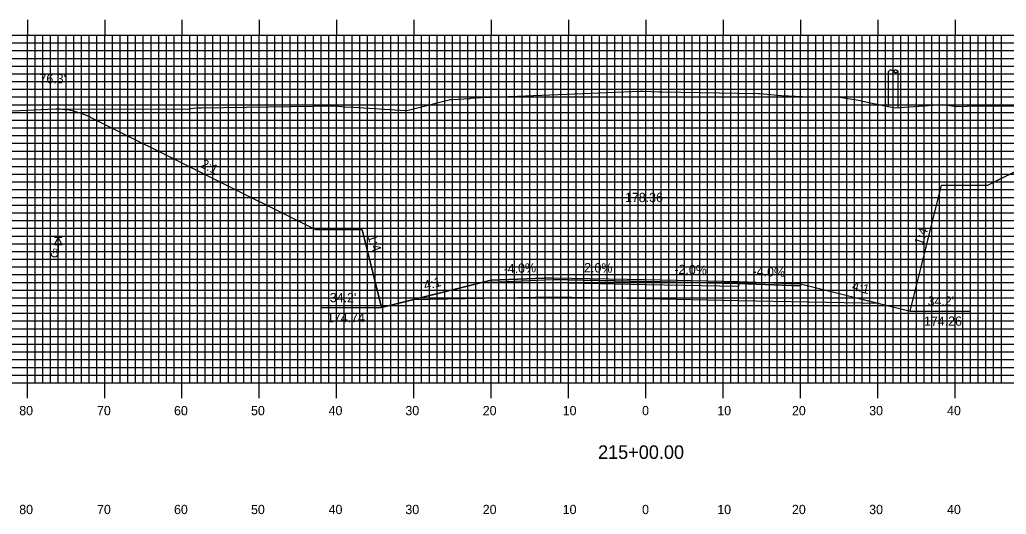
# Model space of a CAD drawing. Extents: x 1796027 to 1796370, y 442591 to 442811.
# Drawn here: x 1796111.4 to 1796239, y 442656.6 to 442720.7 of the extents above; entities that cross this region are included whole.
import ezdxf

# ---------------------------------------------------------------- set-up
doc = ezdxf.new("R2010")
doc.units = 0
for name, color, linetype in [('ANNOTATION', 7, 'Continuous'), ('BORING - REFUSAL', 7, 'Continuous'), ('D_Roadway_Centerline', 7, 'Continuous'), ('D_Roadway_Centerline_Text', 7, 'Continuous'), ('D_Roadway_Edge_Shoulder', 7, 'Continuous'), ('D_Roadway_Edge_TW', 7, 'Continuous'), ('D_Roadway_Pavement', 7, 'Continuous'), ('D_Roadway_SlopeLines', 7, 'Continuous'), ('D_Roadway_SubGrade', 7, 'Continuous'), ('D_Text_Standard', 7, 'Continuous'), ('H_V ANNOTATION', 7, 'Continuous'), ('MAJOR', 7, 'Continuous'), ('MINOR', 7, 'Continuous'), ('PDRAIN', 7, 'Continuous'), ('S_Roadway_Centerline', 7, 'Continuous'), ('S_Utilities_Pole_Power', 7, 'Continuous')]:
    doc.layers.add(name, color=color, linetype=linetype)

msp = doc.modelspace()

# ---------------------------------------------------------------- linework, layer by layer
at = {"layer": 'ANNOTATION'}
for p, q in [((1796236.65, 442699.27), (1796255.09, 442708.49)), ((1796236.65, 442699.27), (1796238.65, 442700.27)), ((1796227.57, 442686.93), (1796230.65, 442699.27)), ((1796230.65, 442699.27), (1796236.65, 442699.27)), ((1796157.22, 442687.41), (1796155.7, 442693.47)), ((1796158.22, 442683.41), (1796157.22, 442687.41)), ((1796226.57, 442682.93), (1796227.57, 442686.93))]:
    msp.add_line(p, q, dxfattribs=at)
msp.add_arc((1796116.09, 442699.09), 10, 63.4349, 90.1255, dxfattribs=at)
msp.add_arc((1796116.09, 442699.09), 10, 63.4349, 90.1255, dxfattribs=at)
at = {"layer": 'BORING - REFUSAL'}
for p, q in [((1796116.87, 442692.47), (1796115.91, 442692.47)), ((1796116.39, 442691.51), (1796116.39, 442690.45))]:
    msp.add_line(p, q, dxfattribs=at)
msp.add_lwpolyline([(1796116.39, 442692.47), (1796116.87, 442691.51), (1796115.91, 442691.51)], close=True, dxfattribs=at)
msp.add_arc((1796115.91, 442690.45), 0.485, 180, 0, dxfattribs=at)
at = {"layer": 'D_Roadway_Centerline'}
msp.add_lwpolyline([(1796155.7, 442693.47), (1796158.22, 442683.41), (1796162.22, 442684.41), (1796172.39, 442686.95), (1796180.39, 442687.27), (1796192.39, 442687.03), (1796204.39, 442686.79), (1796212.39, 442686.47), (1796222.57, 442683.93), (1796226.57, 442682.93), (1796230.65, 442699.27), (1796236.65, 442699.27), (1796255.09, 442708.49)], dxfattribs=at)
at = {"layer": 'D_Roadway_Edge_Shoulder'}
for points in [[(1796180.39, 442687.27), (1796172.39, 442686.95), (1796172.39, 442686.7), (1796180.39, 442687.02)], [(1796204.39, 442686.79), (1796212.39, 442686.47), (1796212.39, 442686.22), (1796204.39, 442686.54)]]:
    msp.add_lwpolyline(points, close=True, dxfattribs=at)
at = {"layer": 'D_Roadway_Edge_TW'}
msp.add_lwpolyline([(1796180.39, 442687.02), (1796180.39, 442687.27), (1796192.39, 442687.03), (1796204.39, 442686.79), (1796204.39, 442686.54), (1796192.39, 442686.78)], close=True, dxfattribs=at)
at = {"layer": 'D_Roadway_Pavement'}
msp.add_lwpolyline([(1796180.39, 442686.6), (1796180.39, 442687.02), (1796192.39, 442686.78), (1796204.39, 442686.54), (1796204.39, 442686.12), (1796192.39, 442686.36)], close=True, dxfattribs=at)
at = {"layer": 'D_Roadway_SlopeLines'}
for points in [[(1796155.7, 442693.47), (1796149.7, 442693.47), (1796120.56, 442708.03)], [(1796172.39, 442686.95), (1796158.22, 442683.41)], [(1796212.39, 442686.47), (1796226.57, 442682.93)]]:
    msp.add_lwpolyline(points, dxfattribs=at)
at = {"layer": 'D_Roadway_SubGrade'}
msp.add_lwpolyline([(1796180.39, 442684.77), (1796162.22, 442684.41), (1796172.39, 442686.95), (1796172.39, 442686.7), (1796180.39, 442687.02), (1796192.39, 442686.78), (1796204.39, 442686.54), (1796212.39, 442686.22), (1796212.39, 442686.47), (1796222.57, 442683.93), (1796204.39, 442684.29), (1796192.39, 442684.53)], close=True, dxfattribs=at)
at = {"layer": 'MAJOR'}
for p, q in [((1796112.39, 442720.67), (1796112.39, 442718.67)), ((1796122.39, 442720.67), (1796122.39, 442718.67)), ((1796132.39, 442720.67), (1796132.39, 442718.67)), ((1796142.39, 442720.67), (1796142.39, 442718.67)), ((1796152.39, 442720.67), (1796152.39, 442718.67)), ((1796162.39, 442720.67), (1796162.39, 442718.67)), ((1796172.39, 442720.67), (1796172.39, 442718.67)), ((1796182.39, 442720.67), (1796182.39, 442718.67)), ((1796192.39, 442720.67), (1796192.39, 442718.67)), ((1796202.39, 442720.67), (1796202.39, 442718.67)), ((1796212.39, 442720.67), (1796212.39, 442718.67)), ((1796222.39, 442720.67), (1796222.39, 442718.67)), ((1796232.39, 442720.67), (1796232.39, 442718.67)), ((1796052.39, 442718.67), (1796332.39, 442718.67)), ((1796052.39, 442718.67), (1796332.39, 442718.67)), ((1796112.39, 442673.67), (1796112.39, 442718.67)), ((1796122.39, 442673.67), (1796122.39, 442718.67)), ((1796132.39, 442673.67), (1796132.39, 442718.67)), ((1796142.39, 442673.67), (1796142.39, 442718.67)), ((1796152.39, 442673.67), (1796152.39, 442718.67)), ((1796162.39, 442673.67), (1796162.39, 442718.67)), ((1796172.39, 442673.67), (1796172.39, 442718.67)), ((1796182.39, 442673.67), (1796182.39, 442718.67)), ((1796192.39, 442673.67), (1796192.39, 442718.67)), ((1796202.39, 442673.67), (1796202.39, 442718.67)), ((1796212.39, 442673.67), (1796212.39, 442718.67)), ((1796222.39, 442673.67), (1796222.39, 442718.67)), ((1796232.39, 442673.67), (1796232.39, 442718.67)), ((1796052.39, 442713.67), (1796332.39, 442713.67)), ((1796052.39, 442708.67), (1796332.39, 442708.67)), ((1796052.39, 442703.67), (1796332.39, 442703.67)), ((1796052.39, 442698.67), (1796332.39, 442698.67)), ((1796052.39, 442693.67), (1796332.39, 442693.67)), ((1796052.39, 442688.67), (1796332.39, 442688.67)), ((1796052.39, 442683.67), (1796332.39, 442683.67)), ((1796052.39, 442678.67), (1796332.39, 442678.67)), ((1796052.39, 442673.67), (1796332.39, 442673.67)), ((1796052.39, 442673.67), (1796332.39, 442673.67)), ((1796112.39, 442671.66), (1796112.39, 442673.67)), ((1796122.39, 442671.66), (1796122.39, 442673.67)), ((1796132.39, 442671.66), (1796132.39, 442673.67)), ((1796142.39, 442671.66), (1796142.39, 442673.67)), ((1796152.39, 442671.66), (1796152.39, 442673.67)), ((1796162.39, 442671.66), (1796162.39, 442673.67)), ((1796172.39, 442671.66), (1796172.39, 442673.67)), ((1796182.39, 442671.66), (1796182.39, 442673.67)), ((1796192.39, 442671.66), (1796192.39, 442673.67)), ((1796202.39, 442671.66), (1796202.39, 442673.67)), ((1796212.39, 442671.66), (1796212.39, 442673.67)), ((1796222.39, 442671.66), (1796222.39, 442673.67)), ((1796232.39, 442671.66), (1796232.39, 442673.67))]:
    msp.add_line(p, q, dxfattribs=at)
at = {"layer": 'MINOR'}
for p, q in [((1796113.39, 442673.67), (1796113.39, 442718.67)), ((1796114.39, 442673.67), (1796114.39, 442718.67)), ((1796115.39, 442673.67), (1796115.39, 442718.67)), ((1796116.39, 442673.67), (1796116.39, 442718.67)), ((1796117.39, 442673.67), (1796117.39, 442718.67)), ((1796118.39, 442673.67), (1796118.39, 442718.67)), ((1796119.39, 442673.67), (1796119.39, 442718.67)), ((1796120.39, 442673.67), (1796120.39, 442718.67)), ((1796121.39, 442673.67), (1796121.39, 442718.67)), ((1796123.39, 442673.67), (1796123.39, 442718.67)), ((1796124.39, 442673.67), (1796124.39, 442718.67)), ((1796125.39, 442673.67), (1796125.39, 442718.67)), ((1796126.39, 442673.67), (1796126.39, 442718.67)), ((1796127.39, 442673.67), (1796127.39, 442718.67)), ((1796128.39, 442673.67), (1796128.39, 442718.67)), ((1796129.39, 442673.67), (1796129.39, 442718.67)), ((1796130.39, 442673.67), (1796130.39, 442718.67)), ((1796131.39, 442673.67), (1796131.39, 442718.67)), ((1796133.39, 442673.67), (1796133.39, 442718.67)), ((1796134.39, 442673.67), (1796134.39, 442718.67)), ((1796135.39, 442673.67), (1796135.39, 442718.67)), ((1796136.39, 442673.67), (1796136.39, 442718.67)), ((1796137.39, 442673.67), (1796137.39, 442718.67)), ((1796138.39, 442673.67), (1796138.39, 442718.67)), ((1796139.39, 442673.67), (1796139.39, 442718.67)), ((1796140.39, 442673.67), (1796140.39, 442718.67)), ((1796141.39, 442673.67), (1796141.39, 442718.67)), ((1796143.39, 442673.67), (1796143.39, 442718.67)), ((1796144.39, 442673.67), (1796144.39, 442718.67)), ((1796145.39, 442673.67), (1796145.39, 442718.67)), ((1796146.39, 442673.67), (1796146.39, 442718.67)), ((1796147.39, 442673.67), (1796147.39, 442718.67)), ((1796148.39, 442673.67), (1796148.39, 442718.67)), ((1796149.39, 442673.67), (1796149.39, 442718.67)), ((1796150.39, 442673.67), (1796150.39, 442718.67)), ((1796151.39, 442673.67), (1796151.39, 442718.67)), ((1796153.39, 442673.67), (1796153.39, 442718.67)), ((1796154.39, 442673.67), (1796154.39, 442718.67)), ((1796155.39, 442673.67), (1796155.39, 442718.67)), ((1796156.39, 442673.67), (1796156.39, 442718.67)), ((1796157.39, 442673.67), (1796157.39, 442718.67)), ((1796158.39, 442673.67), (1796158.39, 442718.67)), ((1796159.39, 442673.67), (1796159.39, 442718.67)), ((1796160.39, 442673.67), (1796160.39, 442718.67)), ((1796161.39, 442673.67), (1796161.39, 442718.67)), ((1796163.39, 442673.67), (1796163.39, 442718.67)), ((1796164.39, 442673.67), (1796164.39, 442718.67)), ((1796165.39, 442673.67), (1796165.39, 442718.67)), ((1796166.39, 442673.67), (1796166.39, 442718.67)), ((1796167.39, 442673.67), (1796167.39, 442718.67)), ((1796168.39, 442673.67), (1796168.39, 442718.67)), ((1796169.39, 442673.67), (1796169.39, 442718.67)), ((1796170.39, 442673.67), (1796170.39, 442718.67)), ((1796171.39, 442673.67), (1796171.39, 442718.67)), ((1796173.39, 442673.67), (1796173.39, 442718.67)), ((1796174.39, 442673.67), (1796174.39, 442718.67)), ((1796175.39, 442673.67), (1796175.39, 442718.67)), ((1796176.39, 442673.67), (1796176.39, 442718.67)), ((1796177.39, 442673.67), (1796177.39, 442718.67)), ((1796178.39, 442673.67), (1796178.39, 442718.67)), ((1796179.39, 442673.67), (1796179.39, 442718.67)), ((1796180.39, 442673.67), (1796180.39, 442718.67)), ((1796181.39, 442673.67), (1796181.39, 442718.67)), ((1796183.39, 442673.67), (1796183.39, 442718.67)), ((1796184.39, 442673.67), (1796184.39, 442718.67)), ((1796185.39, 442673.67), (1796185.39, 442718.67)), ((1796186.39, 442673.67), (1796186.39, 442718.67)), ((1796187.39, 442673.67), (1796187.39, 442718.67)), ((1796188.39, 442673.67), (1796188.39, 442718.67)), ((1796189.39, 442673.67), (1796189.39, 442718.67)), ((1796190.39, 442673.67), (1796190.39, 442718.67)), ((1796191.39, 442673.67), (1796191.39, 442718.67)), ((1796193.39, 442673.67), (1796193.39, 442718.67)), ((1796194.39, 442673.67), (1796194.39, 442718.67)), ((1796195.39, 442673.67), (1796195.39, 442718.67)), ((1796196.39, 442673.67), (1796196.39, 442718.67)), ((1796197.39, 442673.67), (1796197.39, 442718.67)), ((1796198.39, 442673.67), (1796198.39, 442718.67)), ((1796199.39, 442673.67), (1796199.39, 442718.67)), ((1796200.39, 442673.67), (1796200.39, 442718.67)), ((1796201.39, 442673.67), (1796201.39, 442718.67)), ((1796203.39, 442673.67), (1796203.39, 442718.67)), ((1796204.39, 442673.67), (1796204.39, 442718.67)), ((1796205.39, 442673.67), (1796205.39, 442718.67)), ((1796206.39, 442673.67), (1796206.39, 442718.67)), ((1796207.39, 442673.67), (1796207.39, 442718.67)), ((1796208.39, 442673.67), (1796208.39, 442718.67)), ((1796209.39, 442673.67), (1796209.39, 442718.67)), ((1796210.39, 442673.67), (1796210.39, 442718.67)), ((1796211.39, 442673.67), (1796211.39, 442718.67)), ((1796213.39, 442673.67), (1796213.39, 442718.67)), ((1796214.39, 442673.67), (1796214.39, 442718.67)), ((1796215.39, 442673.67), (1796215.39, 442718.67)), ((1796216.39, 442673.67), (1796216.39, 442718.67)), ((1796217.39, 442673.67), (1796217.39, 442718.67)), ((1796218.39, 442673.67), (1796218.39, 442718.67)), ((1796219.39, 442673.67), (1796219.39, 442718.67)), ((1796220.39, 442673.67), (1796220.39, 442718.67)), ((1796221.39, 442673.67), (1796221.39, 442718.67)), ((1796223.39, 442673.67), (1796223.39, 442718.67)), ((1796224.39, 442673.67), (1796224.39, 442718.67)), ((1796225.39, 442673.67), (1796225.39, 442718.67)), ((1796226.39, 442673.67), (1796226.39, 442718.67)), ((1796227.39, 442673.67), (1796227.39, 442718.67)), ((1796228.39, 442673.67), (1796228.39, 442718.67)), ((1796229.39, 442673.67), (1796229.39, 442718.67)), ((1796230.39, 442673.67), (1796230.39, 442718.67)), ((1796231.39, 442673.67), (1796231.39, 442718.67)), ((1796233.39, 442673.67), (1796233.39, 442718.67)), ((1796234.39, 442673.67), (1796234.39, 442718.67)), ((1796235.39, 442673.67), (1796235.39, 442718.67)), ((1796236.39, 442673.67), (1796236.39, 442718.67)), ((1796237.39, 442673.67), (1796237.39, 442718.67)), ((1796238.39, 442673.67), (1796238.39, 442718.67)), ((1796052.39, 442717.67), (1796332.39, 442717.67)), ((1796052.39, 442716.67), (1796332.39, 442716.67)), ((1796052.39, 442715.67), (1796332.39, 442715.67)), ((1796052.39, 442714.67), (1796332.39, 442714.67)), ((1796052.39, 442712.67), (1796332.39, 442712.67)), ((1796052.39, 442711.67), (1796332.39, 442711.67)), ((1796052.39, 442710.67), (1796332.39, 442710.67)), ((1796052.39, 442709.67), (1796332.39, 442709.67)), ((1796052.39, 442707.67), (1796332.39, 442707.67)), ((1796052.39, 442706.67), (1796332.39, 442706.67)), ((1796052.39, 442705.67), (1796332.39, 442705.67)), ((1796052.39, 442704.67), (1796332.39, 442704.67)), ((1796052.39, 442702.67), (1796332.39, 442702.67)), ((1796052.39, 442701.67), (1796332.39, 442701.67)), ((1796052.39, 442700.67), (1796332.39, 442700.67)), ((1796052.39, 442699.67), (1796332.39, 442699.67)), ((1796052.39, 442697.67), (1796332.39, 442697.67)), ((1796052.39, 442696.67), (1796332.39, 442696.67)), ((1796052.39, 442695.67), (1796332.39, 442695.67)), ((1796052.39, 442694.67), (1796332.39, 442694.67)), ((1796052.39, 442692.67), (1796332.39, 442692.67)), ((1796052.39, 442691.67), (1796332.39, 442691.67)), ((1796052.39, 442690.67), (1796332.39, 442690.67)), ((1796052.39, 442689.67), (1796332.39, 442689.67)), ((1796052.39, 442687.67), (1796332.39, 442687.67)), ((1796052.39, 442686.67), (1796332.39, 442686.67)), ((1796052.39, 442685.67), (1796332.39, 442685.67)), ((1796052.39, 442684.67), (1796332.39, 442684.67)), ((1796052.39, 442682.67), (1796332.39, 442682.67)), ((1796052.39, 442681.67), (1796332.39, 442681.67)), ((1796052.39, 442680.67), (1796332.39, 442680.67)), ((1796052.39, 442679.67), (1796332.39, 442679.67)), ((1796052.39, 442677.67), (1796332.39, 442677.67)), ((1796052.39, 442676.67), (1796332.39, 442676.67)), ((1796052.39, 442675.67), (1796332.39, 442675.67)), ((1796052.39, 442674.67), (1796332.39, 442674.67))]:
    msp.add_line(p, q, dxfattribs=at)
at = {"layer": 'PDRAIN'}
for p, q in [((1796150.35, 442683.41), (1796158.22, 442683.41)), ((1796226.57, 442682.93), (1796234.3, 442682.93))]:
    msp.add_line(p, q, dxfattribs=at)
at = {"layer": 'S_Roadway_Centerline'}
msp.add_lwpolyline([(1796110.44, 442708.89), (1796115.06, 442709.09), (1796130.05, 442709.12), (1796132.48, 442709.11), (1796133.28, 442709.13), (1796133.84, 442709.21), (1796134.33, 442709.28), (1796134.89, 442709.27), (1796152.32, 442709.52), (1796153.42, 442709.39), (1796154.62, 442709.37), (1796161.28, 442708.93), (1796161.47, 442708.91), (1796162.69, 442709.21), (1796166.97, 442710.3), (1796167.08, 442710.34), (1796167.43, 442710.35), (1796169.53, 442710.48), (1796169.61, 442710.48), (1796169.77, 442710.52), (1796171.09, 442710.58), (1796174.57, 442710.75), (1796175.73, 442710.79), (1796191.67, 442711.41), (1796191.7, 442711.42), (1796192.04, 442711.41), (1796194.12, 442711.35), (1796194.45, 442711.34), (1796206.92, 442711.1), (1796207.16, 442711.13), (1796209.93, 442710.88), (1796212.65, 442710.71), (1796216.85, 442710.65), (1796217.25, 442710.68), (1796220.13, 442710.22), (1796220.47, 442710.12), (1796221.46, 442709.93), (1796224.63, 442709.28), (1796230.78, 442709.68), (1796232.58, 442709.45), (1796233.96, 442709.48), (1796235.93, 442709.5), (1796236.16, 442709.54), (1796237.54, 442709.5), (1796252.29, 442709.44)], dxfattribs=at)
at = {"layer": 'S_Utilities_Pole_Power'}
for p, q in [((1796223.77, 442713.98), (1796223.93, 442714.09)), ((1796223.77, 442709.36), (1796223.77, 442713.98)), ((1796224.24, 442714.09), (1796224.4, 442713.98)), ((1796224.56, 442714.09), (1796224.4, 442713.98)), ((1796224.4, 442713.98), (1796224.56, 442713.87)), ((1796225.02, 442713.98), (1796224.87, 442714.09)), ((1796224.87, 442713.87), (1796225.02, 442713.98)), ((1796225.02, 442709.36), (1796225.02, 442713.98))]:
    msp.add_line(p, q, dxfattribs=at)
for centre, start, end in [((1796224.09, 442713.87), 90, 125.2644), ((1796224.09, 442713.87), 54.7356, 90), ((1796224.71, 442713.87), 90, 125.2644), ((1796224.71, 442714.09), 234.7356, 270), ((1796224.71, 442713.87), 54.7356, 90), ((1796224.71, 442714.09), 270, 305.2644)]:
    msp.add_arc(centre, 0.271, start, end, dxfattribs=at)

# ---------------------------------------------------------------- texts
at = {"layer": 'ANNOTATION'}
for s, rotation, p in [('2:1', 333.4349, (1796134.7, 442701.62)), ('2:1', 333.4349, (1796134.7, 442701.62)), ('1:4', 70.516, (1796228.2, 442691.38)), ('1:4', 289.484, (1796156.36, 442692.61)), ('-4.0%', 2.2906, (1796174.02, 442687.82)), ('2.0%', 358.8542, (1796184.4, 442687.99)), ('-2.0%', 358.8542, (1796196.08, 442687.76)), ('-4.0%', 357.7094, (1796206.18, 442687.52)), ('4:1', 14.0362, (1796163.84, 442685.67)), ('4:1', 345.9638, (1796218.98, 442685.68))]:
    msp.add_text(s, height=1.2, rotation=rotation, dxfattribs=at).set_placement(p)
for s, p in [("34.2'", (1796151.51, 442684.1)), ("34.2'", (1796228.84, 442683.65)), ('174.74', (1796151.15, 442681.5)), ('174.26', (1796228.38, 442681.05))]:
    msp.add_text(s, height=1.2, dxfattribs=at).set_placement(p)
at = {"layer": 'BORING - REFUSAL'}
msp.add_text('R', height=0.64, dxfattribs=at).set_placement((1796115.68, 442690.39))
at = {"layer": 'D_Roadway_Centerline'}
for s, p in [('C', (1796192.39, 442687.03)), ('L', (1796192.39, 442687.02))]:
    msp.add_text(s, height=0.0146, dxfattribs=at).set_placement(p)
at = {"layer": 'D_Roadway_Centerline_Text'}
msp.add_text('178.36', height=1.2, dxfattribs=at).set_placement((1796189.7, 442697.06))
at = {"layer": 'D_Text_Standard'}
msp.add_text("76.3'", height=1.2, dxfattribs=at).set_placement((1796113.96, 442712.44))
at = {"layer": 'H_V ANNOTATION'}
for s, height, p in [('80', 1.2, (1796111.34, 442669.47)), ('70', 1.2, (1796121.4, 442669.47)), ('60', 1.2, (1796131.36, 442669.47)), ('50', 1.2, (1796141.32, 442669.47)), ('40', 1.2, (1796151.36, 442669.47)), ('30', 1.2, (1796161.29, 442669.47)), ('20', 1.2, (1796171.3, 442669.47)), ('10', 1.2, (1796181.64, 442669.47)), ('0', 1.2, (1796191.91, 442669.47)), ('10', 1.2, (1796201.64, 442669.47)), ('20', 1.2, (1796211.3, 442669.47)), ('30', 1.2, (1796221.29, 442669.47)), ('40', 1.2, (1796231.36, 442669.47)), ('215+00.00', 1.75, (1796186.21, 442663.82)), ('80', 1.2, (1796111.34, 442656.67)), ('70', 1.2, (1796121.4, 442656.67)), ('60', 1.2, (1796131.36, 442656.67)), ('50', 1.2, (1796141.32, 442656.67)), ('40', 1.2, (1796151.36, 442656.67)), ('30', 1.2, (1796161.29, 442656.67)), ('20', 1.2, (1796171.3, 442656.67)), ('10', 1.2, (1796181.64, 442656.67)), ('0', 1.2, (1796191.91, 442656.67)), ('10', 1.2, (1796201.64, 442656.67)), ('20', 1.2, (1796211.3, 442656.67)), ('30', 1.2, (1796221.29, 442656.67)), ('40', 1.2, (1796231.36, 442656.67))]:
    msp.add_text(s, height=height, dxfattribs=at).set_placement(p)

doc.saveas('drawing.dxf')
